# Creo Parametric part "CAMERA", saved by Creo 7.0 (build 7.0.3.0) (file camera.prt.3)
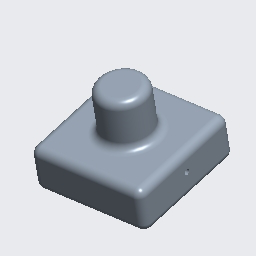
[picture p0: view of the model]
Units: millimeter Kilogram Sec (mmKs); MM, KILOGRAM, SECS

Created from: XX_SOLID_PART_MMKS_ABS.PRT

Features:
  1. coordinate system
  2. datum plane "RIGHT"
  3. datum plane "TOP"
  4. datum plane "FRONT"
  5. extrusion "Extrude 1"
  6. extrusion "Extrude 2"
  7. extruded cut "Extrude 3"
  8. mirror "Mirror 1"
  9. extruded cut "Extrude 3 (2)"
  10. round "Round 1"

Surfaces: 15 cylinder, 12 torus, 9 plane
